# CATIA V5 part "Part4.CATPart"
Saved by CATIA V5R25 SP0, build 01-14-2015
Part number: Part4
Bounding box of the stored display mesh (mm): x 0 to 3, y -5 to 55, z -5 to 5
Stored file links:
  D:\kin uygulama8\Part4.CATPart
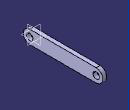
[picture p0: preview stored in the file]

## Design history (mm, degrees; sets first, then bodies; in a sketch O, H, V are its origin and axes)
Body1 (main body)
  Sketch1 on yz-plane, origin (0, 0, 0), H (0, 1, 0), V (0, 0, 1)
    construction line L1 (0, 0) -> (50, 0)
    line L2 (0, 5) -> (50, 5)
    line L3 (50, -5) -> (0, -5)
    arc A1 centre (50, 0) radius 5 from (50, 5) to (50, -5) cw
    arc A2 centre (0, 0) radius 5 from (0, -5) to (0, 5) cw
    circle A3 centre (0, 0) radius 2.5
    circle A4 centre (50, 0) radius 2.5
    distance L1 L2 = 5
    length L1 = 50
    radius A4 = 2.5
    radius A3 = 2.5
    horizontal: L1 H
    tangency: A1 L2, A2 L2, A1 L3, A2 L3
  Pad1: profile Sketch1, direction (1, 0, 0), length 3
